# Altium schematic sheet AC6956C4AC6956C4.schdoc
size 127 x 101 mm
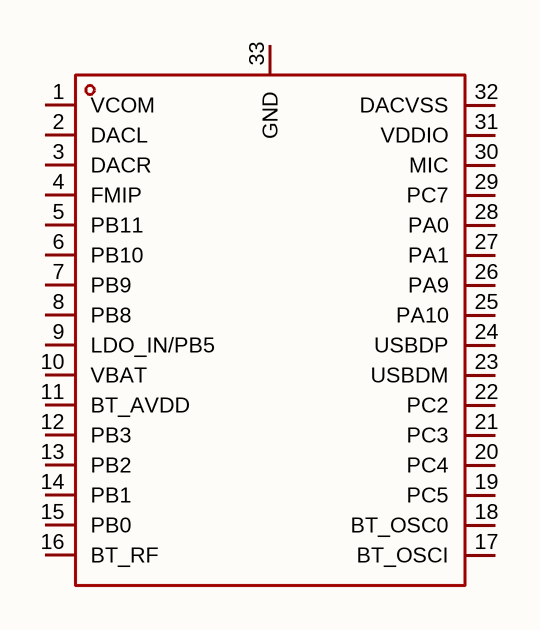
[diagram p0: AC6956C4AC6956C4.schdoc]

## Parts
U?  ac6956c4  [QFN-32_L4.0-W4.0-P0.4-BL-EP2.6]  (value not drawn)

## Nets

Not connected (* = marked no-connect by the designer): U? 1(VCOM) 2(DACL) 3(DACR) 4(FMIP) 5(PB11) 6(PB10) 7(PB9) 8(PB8) 9(LDO_IN/PB5) 10(VBAT) 11(BT_AVDD) 12(PB3) 13(PB2) 14(PB1) 15(PB0) 16(BT_RF) 17(BT_OSCI) 18(BT_OSC0) 19(PC5) 20(PC4) 21(PC3) 22(PC2) 23(USBDM) 24(USBDP) 25(PA10) 26(PA9) 27(PA1) 28(PA0) 29(PC7) 30(MIC) 31(VDDIO) 32(DACVSS) 33(GND)

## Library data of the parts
U? = ac6956c4: CPU内核:-;CPU最大主频:240MHz;CPU位数:32 Bit;; Manufacturer: JL(杰理); AddInBom: yes; ModelId: 2a54fd0a312b4baab982741654358643; ModelName: QFN-32_L4.0-W4.0-H0.8-P0.40; ModelTransform: 158.267,158.267,0,0,0,0,0,0,0; CPU Maximum Speed: 240MHz; Core Size: 32 Bit; ADC (Bit): 16bit; Voltage - Supply: 2.2V~5.5V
